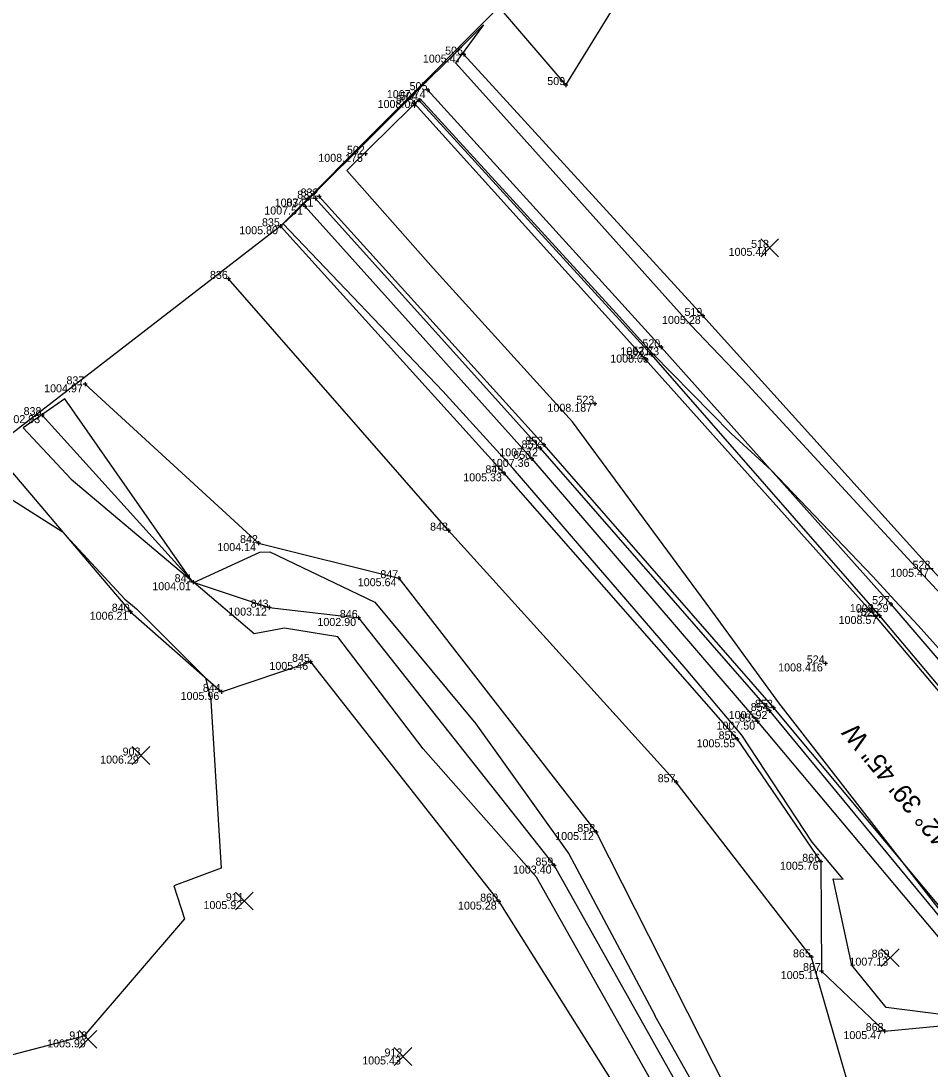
# Model space of a CAD drawing. Extents: x 2354693 to 2355622, y 637071 to 710080.
# Drawn here: x 2355121.1 to 2355257.5, y 709416.4 to 709573.6 of the extents above; entities that cross this region are included whole.
import ezdxf

# ---------------------------------------------------------------- set-up
doc = ezdxf.new("R2010")
doc.units = 0
for name, color, linetype in [('Default', 7, 'Continuous'), ('DR_X_Ditch', 7, 'Continuous'), ('DT_X_Contour_Minor', 7, 'Continuous'), ('PM_X_Surveyed_Line', 7, 'Continuous'), ('PV_X_EOP', 7, 'Continuous'), ('PV_X_Shoulder', 7, 'Continuous'), ('RD_X_Fence', 7, 'Continuous'), ('SV_X_Random_Point', 7, 'Continuous'), ('SV_X_Shot_Marker', 7, 'Continuous'), ('SV_X_Text_Elevation', 7, 'Continuous'), ('SV_X_Text_Name', 7, 'Continuous'), ('SV_X_Toe_of_Slope', 7, 'Continuous'), ('SV_X_Top_of_Bank', 7, 'Continuous'), ('VG_X_Tree_Line_Rt', 7, 'Continuous')]:
    doc.layers.add(name, color=color, linetype=linetype)

msp = doc.modelspace()

# ---------------------------------------------------------------- linework, layer by layer
at = {"layer": 'Default'}
msp.add_lwpolyline([(2355192.85, 709575.71), (2355160.05, 709542.81), (2355116.76, 709509.42), (2355081.06, 709480.43), (2355058.46, 709461.11), (2355065.45, 709426.86), (2355078.86, 709361.48), (2355116.19, 709325.77), (2355146.4, 709319.01), (2355178.16, 709243.86), (2355227.43, 709181.3), (2355213.36, 709127.54), (2355205.69, 709069.16), (2355203.89, 709062.28), (2355168.12, 708973.83)], dxfattribs=at)
msp.add_lwpolyline([(2355192.85, 709575.71), (2355160.05, 709542.81), (2355116.76, 709509.42), (2355081.06, 709480.43), (2355058.46, 709461.11), (2355065.45, 709426.86), (2355078.86, 709361.48), (2355116.19, 709325.77), (2355146.4, 709319.01), (2355178.16, 709243.86), (2355227.43, 709181.3), (2355213.36, 709127.54), (2355205.69, 709069.16), (2355203.89, 709062.28), (2355168.12, 708973.83)], dxfattribs=at)
at = {"layer": 'DR_X_Ditch'}
msp.add_lwpolyline([(2355124.33, 709514.48), (2355146.96, 709489.42), (2355158.35, 709485.61), (2355171.76, 709484.06), (2355201.09, 709446.92), (2355231.21, 709393.32)], dxfattribs=at)
at = {"layer": 'DT_X_Contour_Minor'}
for points in [[(2355262.71, 709424.13), (2355250.91, 709425.61), (2355245.77, 709431.99), (2355242.97, 709444.93), (2355244.48, 709444.86), (2355239.79, 709450.44), (2355229.28, 709466.48), (2355220.89, 709476.36), (2355194.98, 709506.47), (2355184.4, 709518.08), (2355160.48, 709543.16), (2355161.89, 709544.49), (2355162.31, 709544.9), (2355190.53, 709573), (2355186.31, 709567.31), (2355194.48, 709558.28), (2355221.59, 709527.98), (2355230.16, 709519.03), (2355256.51, 709490.43), (2355283.78, 709461.07)], [(2355262.71, 709424.13), (2355250.91, 709425.61), (2355245.77, 709431.99), (2355242.97, 709444.93), (2355244.48, 709444.86), (2355239.79, 709450.44), (2355229.28, 709466.48), (2355220.89, 709476.36), (2355194.98, 709506.47), (2355184.4, 709518.08), (2355160.48, 709543.16), (2355161.89, 709544.49), (2355162.31, 709544.9), (2355190.53, 709573), (2355186.31, 709567.31), (2355194.48, 709558.28), (2355221.59, 709527.98), (2355230.16, 709519.03), (2355256.51, 709490.43), (2355283.78, 709461.07)], [(2355265.88, 709431.37), (2355234.82, 709471.31), (2355225.29, 709484.38), (2355203.88, 709513.49), (2355182.99, 709536.5), (2355170.01, 709551.16), (2355170.43, 709551.59), (2355179.5, 709560.51), (2355180.43, 709561.4), (2355181, 709561.94), (2355210.41, 709529.76), (2355215.87, 709523.72), (2355227.66, 709511.73), (2355233.64, 709506.21), (2355248.86, 709490.32), (2355252.22, 709486.68), (2355255.69, 709482.93), (2355288.36, 709446.53)], [(2355265.88, 709431.37), (2355234.82, 709471.31), (2355225.29, 709484.38), (2355203.88, 709513.49), (2355182.99, 709536.5), (2355170.01, 709551.16), (2355170.43, 709551.59), (2355179.5, 709560.51), (2355180.43, 709561.4), (2355181, 709561.94), (2355210.41, 709529.76), (2355215.87, 709523.72), (2355227.66, 709511.73), (2355233.64, 709506.21), (2355248.86, 709490.32), (2355252.22, 709486.68), (2355255.69, 709482.93), (2355288.36, 709446.53)], [(2355146.78, 709489.61), (2355127.71, 709516.91), (2355121.49, 709512.59), (2355128.66, 709504.85), (2355146.78, 709489.61)], [(2355146.78, 709489.61), (2355127.71, 709516.91), (2355121.49, 709512.59), (2355128.66, 709504.85), (2355146.78, 709489.61)], [(2355136.74, 709486.86), (2355138.47, 709485.41), (2355148.81, 709475.1), (2355149.61, 709471.69), (2355151.16, 709446.51), (2355144.05, 709443.89), (2355145.69, 709438.94), (2355130.58, 709421.31), (2355115.44, 709417.4), (2355117.87, 709430.67), (2355115.64, 709448.31), (2355115.29, 709450.09), (2355103.02, 709481.45), (2355099.82, 709490.6), (2355113.01, 709505.22), (2355116.33, 709503.95), (2355127.34, 709497.01), (2355136.74, 709486.86)], [(2355136.74, 709486.86), (2355138.47, 709485.41), (2355148.81, 709475.1), (2355149.61, 709471.69), (2355151.16, 709446.51), (2355144.05, 709443.89), (2355145.69, 709438.94), (2355130.58, 709421.31), (2355115.44, 709417.4), (2355117.87, 709430.67), (2355115.64, 709448.31), (2355115.29, 709450.09), (2355103.02, 709481.45), (2355099.82, 709490.6), (2355113.01, 709505.22), (2355116.33, 709503.95), (2355127.34, 709497.01), (2355136.74, 709486.86)], [(2355158.48, 709494), (2355174.2, 709486.45), (2355189.39, 709468.18), (2355203.29, 709448.68), (2355216.21, 709424.49), (2355216.18, 709424.48), (2355233.49, 709393.63), (2355230.1, 709392.38), (2355219.1, 709408.53), (2355198.44, 709445.19), (2355181.49, 709464.42), (2355168.68, 709481.23), (2355160.69, 709482.54), (2355156.13, 709481.67), (2355147.07, 709489.38), (2355156.99, 709493.95), (2355158.48, 709494)], [(2355158.48, 709494), (2355174.2, 709486.45), (2355189.39, 709468.18), (2355203.29, 709448.68), (2355216.21, 709424.49), (2355216.18, 709424.48), (2355233.49, 709393.63), (2355230.1, 709392.38), (2355219.1, 709408.53), (2355198.44, 709445.19), (2355181.49, 709464.42), (2355168.68, 709481.23), (2355160.69, 709482.54), (2355156.13, 709481.67), (2355147.07, 709489.38), (2355156.99, 709493.95), (2355158.48, 709494)]]:
    msp.add_lwpolyline(points, dxfattribs=at)
at = {"layer": 'PM_X_Surveyed_Line'}
for points in [[(2355180.15, 709561.24), (2355214.75, 709522.89), (2355249.31, 709484.27), (2355284.02, 709443.14), (2355315.55, 709399.77), (2355328.89, 709377.57), (2355342.97, 709349.79), (2355353.37, 709324.19), (2355361.35, 709299.65), (2355367.76, 709272.47), (2355372.19, 709243.49), (2355373.87, 709217.88), (2355371.21, 709164.41), (2355367.13, 709139.62), (2355360.06, 709111.88), (2355351.62, 709085.78), (2355342.5, 709062.34), (2355329.45, 709031.42), (2355320.62, 709012.58)], [(2355165.86, 709547.27), (2355199.55, 709510.04), (2355233.99, 709470.59), (2355267.54, 709430.37), (2355282.6, 709410.56), (2355297.68, 709388.57), (2355309.4, 709369.45), (2355323.83, 709342.43), (2355334.06, 709318.38), (2355342.29, 709293.43), (2355348.47, 709267.17), (2355351.87, 709240.38), (2355352.96, 709217.38), (2355352.46, 709191.09), (2355350.19, 709167.62), (2355345.96, 709144.01), (2355339.85, 709117.86), (2355332.1, 709093.74), (2355322.6, 709069.08), (2355314.61, 709050.66), (2355300.36, 709021.7)]]:
    msp.add_lwpolyline(points, dxfattribs=at)
at = {"layer": 'PV_X_EOP'}
for points in [[(2355180.81, 709561.74), (2355215.64, 709523.56), (2355249.92, 709484.36), (2355284.41, 709443.36), (2355315.94, 709399.97), (2355329.75, 709378.36), (2355343.52, 709350.1), (2355349.22, 709351.4), (2355359.3, 709326.8), (2355367.59, 709301.75), (2355374.11, 709275.91), (2355368.17, 709272.69), (2355372.5, 709243.56), (2355374.5, 709217.66), (2355371.41, 709164.43), (2355367.84, 709139.33), (2355361.02, 709111.64), (2355352.39, 709085.56), (2355343.44, 709061.97), (2355330.49, 709031.08), (2355321.14, 709011.8)], [(2355165.32, 709546.95), (2355198.99, 709509.5), (2355233.4, 709470.11), (2355266.73, 709429.76), (2355281.93, 709410.08), (2355297.05, 709388.17), (2355308.64, 709369.04), (2355321.45, 709342.93), (2355321.34, 709342.62), (2355331.82, 709317.68), (2355340.04, 709292.97), (2355346.6, 709266.72), (2355349.96, 709239.9), (2355351.76, 709217.38), (2355351.56, 709190.76), (2355349.32, 709167.66), (2355345.61, 709144.12), (2355339.52, 709118.01), (2355331.95, 709093.67), (2355322.31, 709069.24), (2355314.27, 709051.11), (2355300.29, 709022.25)]]:
    msp.add_lwpolyline(points, dxfattribs=at)
at = {"layer": 'PV_X_Shoulder'}
for points in [[(2355182.19, 709563.22), (2355217.16, 709524.65), (2355251.59, 709486.13), (2355286.91, 709444.94), (2355318.24, 709401.51), (2355331.47, 709379.67), (2355345.37, 709350.94)], [(2355163.76, 709545.77), (2355197.77, 709507.92), (2355231.62, 709468.51), (2355264.91, 709428.85), (2355280.65, 709409.06), (2355295.99, 709387.67), (2355307.78, 709368.44), (2355321.17, 709342.6)]]:
    msp.add_lwpolyline(points, dxfattribs=at)
at = {"layer": 'RD_X_Fence'}
msp.add_lwpolyline([(2355192.92, 709575.59), (2355202.86, 709563.98), (2355286.64, 709699.89)], dxfattribs=at)
at = {"layer": 'SV_X_Random_Point'}
for p, q in [((2355232.11, 709538.24), (2355234.78, 709540.91)), ((2355232.11, 709540.91), (2355234.78, 709538.24)), ((2355137.81, 709462.09), (2355140.48, 709464.76)), ((2355137.81, 709464.76), (2355140.48, 709462.09)), ((2355153.31, 709440.27), (2355155.98, 709442.94)), ((2355153.31, 709442.94), (2355155.98, 709440.27)), ((2355250.18, 709431.78), (2355252.85, 709434.45)), ((2355250.18, 709434.45), (2355252.85, 709431.78)), ((2355129.87, 709419.51), (2355132.54, 709422.18)), ((2355129.87, 709422.18), (2355132.54, 709419.51)), ((2355177.1, 709416.95), (2355179.77, 709419.62)), ((2355177.1, 709419.62), (2355179.77, 709416.95))]:
    msp.add_line(p, q, dxfattribs=at)
at = {"layer": 'SV_X_Shot_Marker'}
for p, q in [((2355187.86, 709568.55), (2355187.26, 709568.55)), ((2355187.56, 709568.85), (2355187.56, 709568.25)), ((2355202.86, 709564.28), (2355202.86, 709563.68)), ((2355182.49, 709563.22), (2355181.89, 709563.22)), ((2355182.19, 709563.52), (2355182.19, 709562.92)), ((2355203.16, 709563.98), (2355202.56, 709563.98)), ((2355180.45, 709561.24), (2355179.85, 709561.24)), ((2355180.15, 709561.54), (2355180.15, 709560.94)), ((2355181.11, 709561.74), (2355180.51, 709561.74)), ((2355180.81, 709562.04), (2355180.81, 709561.44)), ((2355173.11, 709553.67), (2355172.51, 709553.67)), ((2355172.81, 709553.97), (2355172.81, 709553.37)), ((2355165.62, 709546.95), (2355165.02, 709546.95)), ((2355165.32, 709547.25), (2355165.32, 709546.65)), ((2355166.16, 709547.27), (2355165.56, 709547.27)), ((2355165.86, 709547.57), (2355165.86, 709546.97)), ((2355164.06, 709545.77), (2355163.46, 709545.77)), ((2355163.76, 709546.07), (2355163.76, 709545.47)), ((2355160.35, 709542.81), (2355159.75, 709542.81)), ((2355160.05, 709543.11), (2355160.05, 709542.51)), ((2355152.59, 709534.91), (2355151.99, 709534.91)), ((2355152.29, 709535.21), (2355152.29, 709534.61)), ((2355223.43, 709529.66), (2355223.43, 709529.06)), ((2355223.73, 709529.36), (2355223.13, 709529.36)), ((2355217.16, 709524.95), (2355217.16, 709524.35)), ((2355215.94, 709523.56), (2355215.34, 709523.56)), ((2355215.64, 709523.86), (2355215.64, 709523.26)), ((2355217.46, 709524.65), (2355216.86, 709524.65)), ((2355215.05, 709522.89), (2355214.45, 709522.89)), ((2355214.75, 709523.19), (2355214.75, 709522.59)), ((2355131.06, 709519.1), (2355130.46, 709519.1)), ((2355130.76, 709519.4), (2355130.76, 709518.8)), ((2355207.51, 709516.19), (2355206.91, 709516.19)), ((2355207.21, 709516.49), (2355207.21, 709515.89)), ((2355124.63, 709514.48), (2355124.03, 709514.48)), ((2355124.33, 709514.78), (2355124.33, 709514.18)), ((2355199.29, 709509.5), (2355198.69, 709509.5)), ((2355198.99, 709509.8), (2355198.99, 709509.2)), ((2355199.85, 709510.04), (2355199.25, 709510.04)), ((2355199.55, 709510.34), (2355199.55, 709509.74)), ((2355198.07, 709507.92), (2355197.47, 709507.92)), ((2355197.77, 709508.22), (2355197.77, 709507.62)), ((2355193.59, 709506.05), (2355193.59, 709505.45)), ((2355193.89, 709505.75), (2355193.29, 709505.75)), ((2355185.59, 709497.16), (2355184.99, 709497.16)), ((2355185.29, 709497.46), (2355185.29, 709496.86)), ((2355157.07, 709495.29), (2355156.47, 709495.29)), ((2355156.77, 709495.59), (2355156.77, 709494.99)), ((2355177.83, 709490.32), (2355177.83, 709489.72)), ((2355257.96, 709491.43), (2355257.36, 709491.43)), ((2355147.26, 709489.42), (2355146.66, 709489.42)), ((2355146.96, 709489.72), (2355146.96, 709489.12)), ((2355178.13, 709490.02), (2355177.53, 709490.02)), ((2355158.65, 709485.61), (2355158.05, 709485.61)), ((2355158.35, 709485.91), (2355158.35, 709485.31)), ((2355251.89, 709486.13), (2355251.29, 709486.13)), ((2355251.59, 709486.43), (2355251.59, 709485.83)), ((2355137.88, 709484.99), (2355137.28, 709484.99)), ((2355137.58, 709485.29), (2355137.58, 709484.69)), ((2355172.06, 709484.06), (2355171.46, 709484.06)), ((2355171.76, 709484.36), (2355171.76, 709483.76)), ((2355249.61, 709484.27), (2355249.01, 709484.27)), ((2355249.31, 709484.57), (2355249.31, 709483.97)), ((2355250.22, 709484.36), (2355249.62, 709484.36)), ((2355249.92, 709484.66), (2355249.92, 709484.06)), ((2355164.56, 709477.77), (2355164.56, 709477.17)), ((2355164.86, 709477.47), (2355164.26, 709477.47)), ((2355242.12, 709477.24), (2355241.52, 709477.24)), ((2355241.82, 709477.54), (2355241.82, 709476.94)), ((2355151.24, 709473.27), (2355151.24, 709472.67)), ((2355151.54, 709472.97), (2355150.94, 709472.97)), ((2355233.7, 709470.11), (2355233.1, 709470.11)), ((2355233.4, 709470.41), (2355233.4, 709469.81)), ((2355234.29, 709470.59), (2355233.69, 709470.59)), ((2355233.99, 709470.89), (2355233.99, 709470.29)), ((2355231.92, 709468.51), (2355231.32, 709468.51)), ((2355231.62, 709468.81), (2355231.62, 709468.21)), ((2355228.88, 709465.86), (2355228.28, 709465.86)), ((2355228.58, 709466.16), (2355228.58, 709465.56)), ((2355219.73, 709459.42), (2355219.13, 709459.42)), ((2355219.43, 709459.72), (2355219.43, 709459.12)), ((2355207.69, 709451.95), (2355207.09, 709451.95)), ((2355207.39, 709452.25), (2355207.39, 709451.65)), ((2355201.39, 709446.92), (2355200.79, 709446.92)), ((2355201.09, 709447.22), (2355201.09, 709446.62)), ((2355241.42, 709447.49), (2355240.82, 709447.49)), ((2355241.12, 709447.79), (2355241.12, 709447.19)), ((2355192.83, 709441.82), (2355192.83, 709441.22)), ((2355193.13, 709441.52), (2355192.53, 709441.52)), ((2355240, 709433.16), (2355239.4, 709433.16)), ((2355239.7, 709433.46), (2355239.7, 709432.86)), ((2355241.52, 709431.1), (2355240.92, 709431.1)), ((2355241.22, 709431.4), (2355241.22, 709430.8)), ((2355250.94, 709422.1), (2355250.34, 709422.1)), ((2355250.64, 709422.4), (2355250.64, 709421.8))]:
    msp.add_line(p, q, dxfattribs=at)
at = {"layer": 'SV_X_Toe_of_Slope'}
for points in [[(2355187.56, 709568.55), (2355223.43, 709529.36), (2355257.66, 709491.43), (2355294.21, 709452.95), (2355332.81, 709410.94), (2355352.9, 709375.39), (2355357.05, 709369.03), (2355359.18, 709363.17)], [(2355160.05, 709542.81), (2355193.59, 709505.75), (2355228.58, 709465.86), (2355241.12, 709447.49), (2355241.22, 709431.1), (2355250.64, 709422.1), (2355263.74, 709423.31), (2355276.08, 709404.25), (2355290.87, 709383.79), (2355296.26, 709362.73), (2355304.65, 709343.07)]]:
    msp.add_lwpolyline(points, dxfattribs=at)
at = {"layer": 'SV_X_Top_of_Bank'}
for points in [[(2355130.76, 709519.1), (2355156.77, 709495.29), (2355177.83, 709490.02), (2355207.39, 709451.95), (2355236.75, 709394.01)], [(2355116.76, 709509.42), (2355137.58, 709484.99), (2355151.24, 709472.97), (2355164.56, 709477.47), (2355192.83, 709441.52), (2355225.93, 709388.87), (2355236.65, 709394.06)]]:
    msp.add_lwpolyline(points, dxfattribs=at)
at = {"layer": 'VG_X_Tree_Line_Rt'}
msp.add_lwpolyline([(2355286.87, 709031.33), (2355312.43, 709075.83), (2355322.75, 709120.09), (2355304.91, 709171.78), (2355297.85, 709210.36), (2355206.48, 709334.22), (2355207.86, 709373.6), (2355249.36, 709399.77), (2355239.7, 709433.16), (2355219.43, 709459.42), (2355185.29, 709497.16), (2355152.29, 709534.91)], dxfattribs=at)

# ---------------------------------------------------------------- texts
at = {"layer": 'Default'}
msp.add_text('N 42%%d 39\' 45" W', height=2.8, rotation=129.6098, dxfattribs=at).set_placement((2355263.1, 709448.16))
at = {"layer": 'SV_X_Text_Elevation'}
for s, p in [('1005.47', (2355181.42, 709567.35)), ('1007.74', (2355176.02, 709562.02)), ('1008.04', (2355174.64, 709560.54)), ('1008.175', (2355165.74, 709552.47)), ('1007.71', (2355159.2, 709545.75)), ('1007.51', (2355157.64, 709544.57)), ('1005.80', (2355153.89, 709541.61)), ('1005.44', (2355227.28, 709538.37)), ('1005.28', (2355217.29, 709528.16)), ('1008.05', (2355209.53, 709522.36)), ('1007.73', (2355211.05, 709523.45)), ('1004.97', (2355124.62, 709517.9)), ('1008.187', (2355200.11, 709514.99)), ('1002.93', (2355118.22, 709513.28)), ('1007.72', (2355192.88, 709508.3)), ('1007.36', (2355191.62, 709506.72)), ('1005.33', (2355187.48, 709504.55)), ('1004.14', (2355150.6, 709494.09)), ('1005.47', (2355251.52, 709490.23)), ('1004.01', (2355140.84, 709488.22)), ('1005.64', (2355171.66, 709488.82)), ('1003.12', (2355152.23, 709484.41)), ('1008.29', (2355245.46, 709484.93)), ('1006.21', (2355131.46, 709483.79)), ('1002.90', (2355165.61, 709482.86)), ('1008.57', (2355243.78, 709483.16)), ('1005.46', (2355158.41, 709476.27)), ('1008.416', (2355234.71, 709476.04)), ('1005.96', (2355145.09, 709471.77)), ('1007.92', (2355227.29, 709468.91)), ('1007.50', (2355225.46, 709467.31)), ('1005.55', (2355222.47, 709464.66)), ('1006.29', (2355133.02, 709462.22)), ('1005.12', (2355201.27, 709450.75)), ('1003.40', (2355194.93, 709445.72)), ('1005.76', (2355234.97, 709446.29)), ('1005.92', (2355148.52, 709440.4)), ('1005.28', (2355186.69, 709440.32)), ('1007.13', (2355245.4, 709431.91)), ('1005.11', (2355235.1, 709429.9)), ('1005.47', (2355244.5, 709420.9)), ('1005.99', (2355125.07, 709419.65)), ('1005.43', (2355172.33, 709417.09))]:
    msp.add_text(s, height=1.2, dxfattribs=at).set_placement(p)
at = {"layer": 'SV_X_Text_Name'}
for s, p in [('506', (2355184.76, 709568.55)), ('505', (2355179.43, 709563.22)), ('509', (2355200.08, 709563.98)), ('504', (2355177.99, 709561.74)), ('503', (2355177.39, 709561.24)), ('502', (2355170.04, 709553.67)), ('832', (2355163.09, 709547.27)), ('834', (2355160.94, 709545.77)), ('833', (2355162.57, 709546.95)), ('835', (2355157.29, 709542.81)), ('518', (2355230.65, 709539.57)), ('836', (2355149.49, 709534.91)), ('519', (2355220.66, 709529.36)), ('520', (2355214.35, 709524.65)), ('522', (2355211.98, 709522.89)), ('521', (2355212.87, 709523.56)), ('837', (2355127.97, 709519.1)), ('523', (2355204.45, 709516.19)), ('838', (2355121.54, 709514.48)), ('851', (2355196.22, 709509.5)), ('852', (2355196.78, 709510.04)), ('850', (2355194.97, 709507.92)), ('849', (2355190.81, 709505.75)), ('848', (2355182.5, 709497.16)), ('842', (2355154, 709495.29)), ('528', (2355254.86, 709491.43)), ('841', (2355144.19, 709489.42)), ('847', (2355175.05, 709490.02)), ('527', (2355248.8, 709486.13)), ('840', (2355134.77, 709484.99)), ('843', (2355155.59, 709485.61)), ('526', (2355247.12, 709484.36)), ('846', (2355168.97, 709484.06)), ('525', (2355246.54, 709484.27)), ('845', (2355161.8, 709477.47)), ('524', (2355239, 709477.24)), ('844', (2355148.42, 709472.97)), ('853', (2355231.24, 709470.59)), ('854', (2355230.59, 709470.11)), ('855', (2355228.86, 709468.51)), ('856', (2355225.78, 709465.86)), ('903', (2355136.39, 709463.42)), ('857', (2355216.64, 709459.42)), ('858', (2355204.59, 709451.95)), ('859', (2355198.31, 709446.92)), ('866', (2355238.32, 709447.49)), ('911', (2355151.87, 709441.6)), ('860', (2355190.02, 709441.52)), ('865', (2355236.93, 709433.16)), ('869', (2355248.73, 709433.11)), ('867', (2355238.44, 709431.1)), ('868', (2355247.84, 709422.1)), ('910', (2355128.39, 709420.85)), ('912', (2355175.67, 709418.29))]:
    msp.add_text(s, height=1.2, dxfattribs=at).set_placement(p)

doc.saveas('drawing.dxf')
